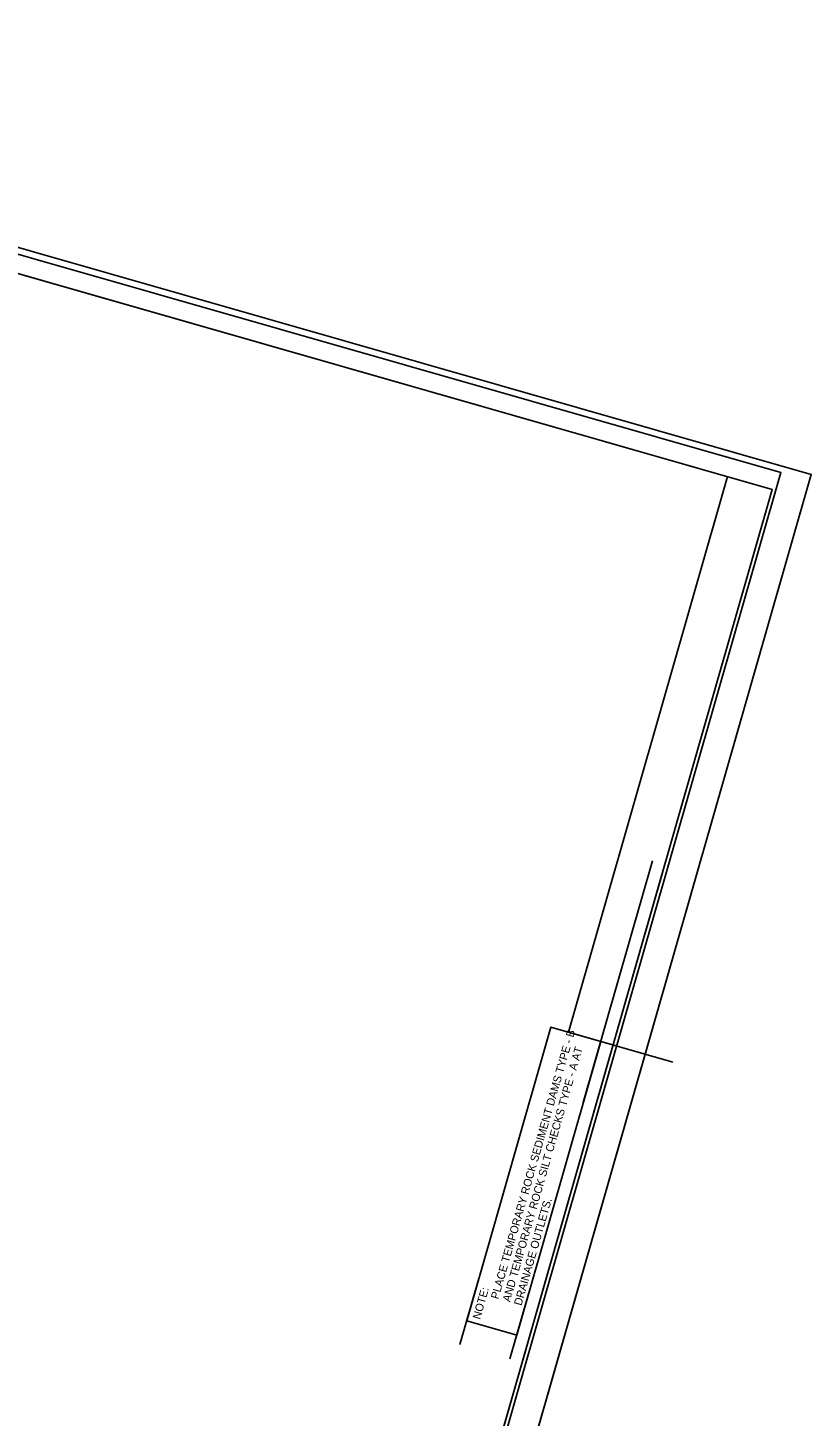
# Model space of a CAD drawing. Extents: x 2096934 to 2098492, y 687716 to 689682.
# Drawn here: x 2097963 to 2098492, y 688699 to 689636 of the extents above; entities that cross this region are included whole.
import ezdxf

# ---------------------------------------------------------------- set-up
doc = ezdxf.new("R2010")
doc.units = 0
for name, color, linetype in [('Prop Drainage Structure Catch Basin Grate 840 03F CELL', 7, 'Continuous'), ('Prop Drainage Structure Manhole Adjust CELL', 7, 'Continuous'), ('Prop Drainage Structure Outlet Generic CELL', 7, 'Continuous'), ('Prop Drainage Structure Plot Symbol 20 Scale', 7, 'Continuous'), ('Scratch_Level_0', 7, 'Continuous'), ('Scratch_Level_3', 7, 'Continuous'), ('Sheet Clip Boundary CELL', 7, 'Continuous')]:
    doc.layers.add(name, color=color, linetype=linetype)

msp = doc.modelspace()

# ---------------------------------------------------------------- linework, layer by layer
at = {"layer": 'Prop Drainage Structure Catch Basin Grate 840 03F CELL'}
msp.add_line((2098028.44, 687715.97), (2098491.74, 689334.46), dxfattribs=at)
at = {"layer": 'Prop Drainage Structure Manhole Adjust CELL'}
for p, q in [((2098435.32, 689332.93), (2098327.99, 688957.99)), ((2098337.99, 688910.64), (2098384.68, 689073.75)), ((2098344.95, 688903.45), (2098391.64, 689066.57)), ((2098327.99, 688957.99), (2098398.38, 688937.84)), ((2098267.48, 688791.82), (2098254.74, 688747.32)), ((2098301.23, 688782.16), (2098288.49, 688737.66)), ((2098259.3, 688763.3), (2098293.07, 688753.64))]:
    msp.add_line(p, q, dxfattribs=at)
at = {"layer": 'Prop Drainage Structure Outlet Generic CELL'}
msp.add_lwpolyline([(2098028.44, 687715.97), (2098491.74, 689334.46), (2097439.02, 689635.81), (2096975.72, 688017.32)], close=True, dxfattribs=at)
at = {"layer": 'Prop Drainage Structure Plot Symbol 20 Scale'}
msp.add_lwpolyline([(2098012.79, 687733.97), (2098471.26, 689335.63), (2097457.01, 689625.98), (2096998.53, 688024.31)], close=True, dxfattribs=at)
at = {"layer": 'Scratch_Level_0'}
msp.add_lwpolyline([(2098259.31, 688763.3), (2098316.02, 688961.41), (2098349.76, 688951.76), (2098293.07, 688753.64)], close=True, dxfattribs=at)
at = {"layer": 'Scratch_Level_3'}
for points in [[(2097455.97, 689613.3), (2097043.16, 688171.19), (2098052.61, 687882.22), (2098465.42, 689324.31)], [(2098052.61, 687882.22), (2097043.17, 688171.15), (2097400.9, 689420.95), (2097545.17, 689379.67), (2097600.23, 689571.98), (2098465.42, 689324.31)]]:
    msp.add_lwpolyline(points, close=True, dxfattribs=at)
at = {"layer": 'Sheet Clip Boundary CELL'}
for points in [[(2098102.1, 688055.1), (2097347.73, 688084.03), (2097043.16, 688171.19), (2097346.07, 689229.4), (2097355.46, 689262.19), (2097400.9, 689420.95), (2097628.1, 689355.93), (2097683.15, 689548.26), (2098465.42, 689324.31)], [(2098102.1, 688055.1), (2097347.73, 688084.03), (2097043.16, 688171.19), (2097345.95, 689228.93), (2097355.46, 689262.19), (2097400.91, 689420.95), (2097628.1, 689355.93), (2097683.15, 689548.26), (2098465.42, 689324.31)]]:
    msp.add_lwpolyline(points, close=True, dxfattribs=at)

# ---------------------------------------------------------------- texts
at = {"layer": 'Scratch_Level_0'}
for s, p in [('PLACE TEMPORARY ROCK SEDIMENT DAMS TYPE - B', (2098280.68, 688777.5)), ('AND TEMPORARY ROCK SILT CHECKS TYPE - A AT', (2098288.53, 688775.64)), ('DRAINAGE OUTLETS.', (2098296.25, 688773.16)), ('NOTE:', (2098268.36, 688763.88))]:
    msp.add_text(s, height=5.4, rotation=74.03119, dxfattribs=at).set_placement(p)

doc.saveas('drawing.dxf')
